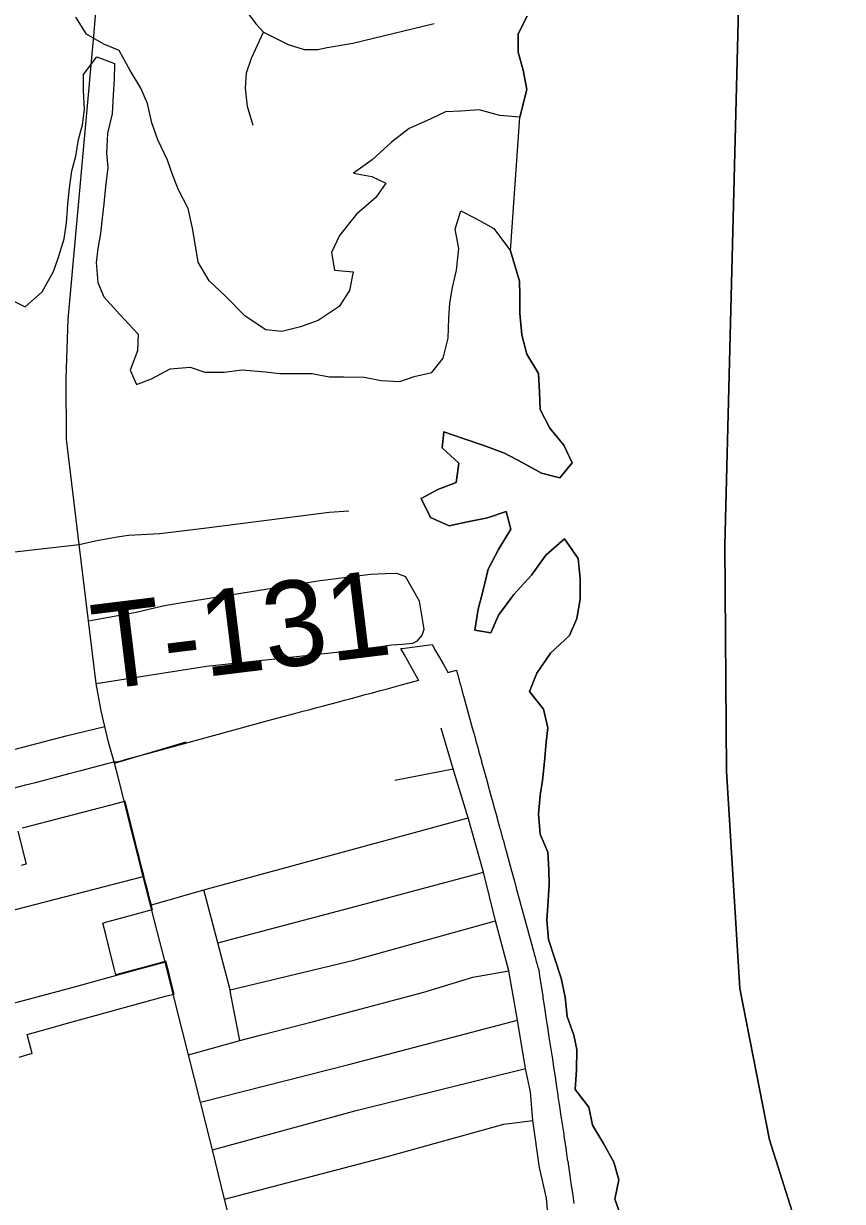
# Model space of a CAD drawing. Extents: x 114843 to 284848, y 317643 to 566895.
# Drawn here: x 167440 to 170319, y 459640 to 463781 of the extents above; entities that cross this region are included whole.
import ezdxf

# ---------------------------------------------------------------- set-up
doc = ezdxf.new("R2010")
doc.units = 0
for name, color, linetype in [('GM_X_City_Street', 7, 'Continuous'), ('GM_X_Corporation', 7, 'Continuous'), ('GM_X_County_Road', 7, 'Continuous'), ('GM_X_Major_Lake', 7, 'Continuous'), ('GM_X_Major_River', 7, 'Continuous'), ('GM_X_State_Route', 7, 'Continuous'), ('GM_X_Township', 7, 'Continuous'), ('GM_X_Township_Road', 7, 'Continuous'), ('GM_X_Township_Road_Text', 7, 'Continuous')]:
    doc.layers.add(name, color=color, linetype=linetype)

msp = doc.modelspace()

# ---------------------------------------------------------------- linework, layer by layer
at = {"layer": 'GM_X_City_Street'}
for p, q in [((168745.7, 461121), (168950.7, 461161.4)), ((168200, 460205.8), (168169.3, 460367.8))]:
    msp.add_line(p, q, dxfattribs=at)
for points in [[(168967.3, 461107.1), (168950.7, 461161.4), (168908.5, 461303.7)], [(169468.8, 458354.7), (169437.7, 458431.6), (169429.4, 458486), (169425.1, 458527.2), (169427.4, 458612.6), (169413.6, 458710.9), (169362.2, 459060.9), (169338.5, 459258.1), (169309.4, 459413), (169285.1, 459584.6), (169278.4, 459651.4), (169254.4, 459760), (169230.9, 459924.5), (169222.5, 460025.5), (169205.1, 460108.1), (169176.3, 460277.9), (169146.9, 460451.4), (169099.9, 460627), (169057.2, 460797.9), (169003.6, 460988.7), (168967.3, 461107.1)], [(167885.9, 460681.7), (168073.6, 460735), (168750, 460920.1), (169003.6, 460988.7)], [(168123.6, 460549.6), (168623.7, 460681.2), (169057.2, 460797.9)], [(168169.3, 460367.8), (168166.2, 460384), (168123.6, 460549.6), (168073.6, 460735)], [(168166.2, 460384), (168601.6, 460488.1), (169099.9, 460627)], [(168989.8, 460418.9), (169020.3, 460428.1), (169146.9, 460451.4)], [(168276.2, 460225.4), (168459, 460272.6), (168847.6, 460376.3), (168989.8, 460418.9)], [(168061.8, 459989.1), (168583.4, 460122), (169176.3, 460277.9)], [(168019.9, 460155.2), (168200, 460205.8), (168276.2, 460225.4)], [(168104.4, 459821.6), (168609.8, 459960.5), (169205.1, 460108.1)], [(168146.6, 459648), (168715.3, 459797), (169128.3, 459911.4), (169230.9, 459924.5)]]:
    msp.add_lwpolyline(points, dxfattribs=at)
at = {"layer": 'GM_X_Corporation'}
for points in [[(167404.1, 461092.8), (167442.9, 461103), (167447.2, 461104.1), (167482.5, 461113.4), (167521.5, 461123.7), (167539.8, 461128.5), (167561.6, 461134.2), (167600.6, 461144.5), (167641.7, 461155.4), (167730, 461178.9), (167732.7, 461179.6), (167739.3, 461181.3), (167761.8, 461187.2), (167762.6, 461183.8), (167791.5, 461191.7), (167797.9, 461193.5), (167902.3, 461222), (168253, 461317.8), (168295.2, 461329.3), (168397.7, 461356.7), (168422.2, 461363.2), (168447.5, 461370), (168471.2, 461376.3), (168494.6, 461382.5), (168543.9, 461395.7), (168568.6, 461402.3), (168592.3, 461408.7), (168618, 461415.5), (168641.3, 461421.7), (168667, 461428.6), (168690.4, 461434.9), (168715.2, 461441.5), (168739.5, 461448), (168763.7, 461454.5), (168829.4, 461472), (168828, 461474.6), (168805.2, 461515.1), (168792.3, 461538.1), (168779.3, 461561.3), (168767, 461583.3), (168771.1, 461583.8), (168877.1, 461597.5), (168889, 461576.2), (168902.2, 461552.7), (168915.2, 461529.6), (168930.4, 461502.6), (168932.1, 461499.4), (168962, 461507.4), (168964.8, 461497.7), (168965.7, 461494.5), (168975.6, 461459), (168976.5, 461455.7), (168986.3, 461420.3), (168987.2, 461417.1), (168996.8, 461382.2), (168997.6, 461379), (169007.4, 461343.6), (169008.3, 461340.4), (169018, 461305), (169018.9, 461301.8), (169028.6, 461266.4), (169029.5, 461263.1), (169039.3, 461227.6), (169040.2, 461224.3), (169049.9, 461189), (169050.8, 461185.8), (169060.9, 461148.8), (169061.8, 461145.6), (169071, 461112.1), (169071.5, 461110.3), (169082.4, 461070.7), (169092.4, 461034.1), (169092.8, 461032.3), (169103.6, 460992.9), (169104.1, 460991.1), (169115.1, 460951), (169115.6, 460949.2), (169125.6, 460912.6), (169126.1, 460910.8), (169136, 460874.7), (169136.5, 460873), (169147.6, 460832.3), (169155.7, 460802.6), (169156.8, 460798.8), (169164.7, 460769.8), (169165.7, 460766), (169173.8, 460736.5), (169174.9, 460732.7), (169183, 460702.8), (169184.1, 460699), (169192.4, 460668.7), (169193.4, 460664.9), (169201.5, 460635.3), (169202.5, 460631.7), (169210.8, 460601.4), (169211.8, 460597.6), (169217.9, 460575.4), (169220.1, 460567.3), (169221.2, 460563.5), (169229.5, 460533.1), (169237.7, 460503), (169238.8, 460499.2), (169242.9, 460484), (169244.6, 460478), (169248.7, 460462.7), (169249.3, 460461), (169251.6, 460453.3), (169255.9, 460425), (169261.1, 460391.2), (169265.5, 460362.4), (169266.4, 460356.3), (169271.6, 460322), (169277, 460287.3), (169281.4, 460258.4), (169282.3, 460252.3), (169287.5, 460217.9), (169292.9, 460183), (169297.3, 460154.2), (169298.2, 460148), (169303.5, 460113.3), (169307.8, 460084.4), (169308.8, 460078.2), (169314, 460043.4), (169318.3, 460014.9), (169319.2, 460008.7), (169324.4, 459974.2), (169329.6, 459939.8), (169333.9, 459911.7), (169334.8, 459905.3), (169339.2, 459876.6), (169340.1, 459870.2), (169345.3, 459835.7), (169350.6, 459799.4), (169352, 459790.1), (169352.9, 459783.7), (169353.3, 459781.4), (169355.8, 459764.1), (169360.5, 459732), (169364.6, 459703.9), (169365.5, 459697.5), (169370.8, 459661.5), (169374.9, 459632.9)], [(167424.2, 460147.9), (167463.3, 460158.8), (167469.9, 460160.6), (167452.9, 460227.4), (167524.7, 460247.2), (167602.3, 460268.7), (167938.9, 460361.7), (167969.9, 460368.7), (167959.1, 460410.4), (167950.3, 460444.5), (167940, 460484.4), (167908.7, 460475.8), (167764.6, 460436.3), (167759.5, 460455.7), (167749.2, 460497.1), (167739.5, 460535.8), (167729, 460578.2), (167718.9, 460618.7), (167733.1, 460622.6), (167767.9, 460632.3), (167862.7, 460658.8), (167892.9, 460666.4), (167888.2, 460685.1), (167884.2, 460701.1), (167875.7, 460735), (167865.6, 460774.7), (167862.9, 460785.5), (167856.4, 460811.2), (167847.7, 460845.8), (167838.8, 460881.2), (167830.1, 460915.7), (167817.3, 460966.6), (167804.2, 461018.8), (167797.7, 461046.8), (167769.6, 461039.6), (167435, 460951.8)], [(167419.5, 460941.6), (167449.4, 460826.1), (167447.6, 460825.6), (167431.7, 460821.3)]]:
    msp.add_lwpolyline(points, dxfattribs=at)
at = {"layer": 'GM_X_County_Road'}
msp.add_lwpolyline([(166273, 461789.7), (166413.7, 461807.2), (166482.1, 461815), (166760.2, 461849.3), (166977.2, 461874.1), (167064.3, 461883.6), (167229, 461903.7), (167325.4, 461914.8), (167635.9, 461949.3)], dxfattribs=at)
at = {"layer": 'GM_X_Major_Lake'}
msp.add_line((169152.1, 462982.1), (169185.5, 463451), dxfattribs=at)
for points in [[(169185.5, 463451), (169209.4, 463548.3), (169197.2, 463616.4), (169179, 463680.5), (169178.8, 463744.5), (169210.7, 463806.7)], [(169541.6, 459585.7), (169519.4, 459647.8), (169533.2, 459716), (169515, 459778), (169478.7, 459844.1), (169440.4, 459908.1), (169428.2, 459972.2), (169379.9, 460034.2), (169383.7, 460102.4), (169385.5, 460174.5), (169375.3, 460224.6), (169351.1, 460290.7), (169344.9, 460358.8), (169330.6, 460424.9), (169306.4, 460497), (169286.1, 460561.1), (169279.9, 460629.2), (169283.8, 460679.3), (169287.6, 460753.5), (169287.4, 460805.5), (169283.3, 460867.7), (169257, 460931.7), (169250.8, 461001.9), (169256.6, 461068), (169264.5, 461120.1), (169272.3, 461186.3), (169278.1, 461254.4), (169284, 461304.5), (169267.8, 461370.6), (169219.5, 461432.6), (169245.3, 461496.8), (169293.3, 461567.1), (169359.3, 461629.3), (169385.2, 461689.5), (169397, 461757.7), (169396.8, 461829.8), (169390.6, 461899.9), (169342.3, 461969.9), (169276.2, 461911.7), (169226.3, 461841.4), (169164.3, 461773.1), (169110.4, 461700.8), (169082.5, 461638.7), (169026.3, 461648.5), (169038.2, 461722.7), (169056, 461788.9), (169073.8, 461863.1), (169109.8, 461931.3), (169153.7, 462003.5), (169137.4, 462065.6), (169071.3, 462043.4), (169001.2, 462029.2), (168937, 462015), (168870.8, 462044.9), (168838.5, 462110.9), (168896.6, 462143.1), (168960.7, 462167.3), (168970.5, 462235.5), (168912.2, 462289.4), (168918.1, 462345.5), (168986.3, 462321.7), (169058.6, 462297.8), (169130.8, 462269.9), (169195.1, 462236.1), (169261.4, 462200.2), (169325.6, 462184.3), (169369.6, 462236.5), (169339.3, 462298.5), (169291, 462358.5), (169256.7, 462424.5), (169254.6, 462484.7), (169250.4, 462550.8), (169210.1, 462618.8), (169191.8, 462686.8), (169185.6, 462761), (169185.4, 462825.1), (169183.3, 462875.1), (169152.1, 462982.1)]]:
    msp.add_lwpolyline(points, dxfattribs=at)
at = {"layer": 'GM_X_Major_River'}
msp.add_line((169152.1, 462982.1), (169185.5, 463451), dxfattribs=at)
for points in [[(168523, 462975.7), (168533.4, 462913.7), (168599.5, 462907.9), (168585.8, 462841.8), (168550, 462785.5), (168476, 462737.1), (168414, 462714.8), (168347.9, 462698.4), (168291.7, 462704.2), (168219.3, 462752), (168148.9, 462823.8), (168092.5, 462875.7), (168054.1, 462941.7), (168045.9, 462991.7), (168033.6, 463061.8), (168019.2, 463129.9), (167984.9, 463195.8), (167964.6, 463245.9), (167946.3, 463299.9), (167911.9, 463371.9), (167891.6, 463431.9), (167875.3, 463500), (167853, 463554), (167814.6, 463615.9), (167776.3, 463685.9), (167722, 463707.7), (167661.7, 463743.5), (167623.4, 463803.4)], [(169210.7, 463806.7), (169178.8, 463744.5), (169179, 463680.5), (169197.2, 463616.4), (169209.4, 463548.3), (169185.5, 463451)], [(167377.1, 462820.5), (167445.4, 462784.7), (167505.4, 462837.1), (167545.1, 462909.4), (167562.9, 462959.6), (167582.7, 463023.8), (167590.5, 463079.9), (167596.2, 463146.1), (167602, 463202.2), (167609.7, 463262.4), (167623.5, 463314.5), (167633.3, 463372.7), (167647.1, 463424.8), (167654.9, 463479), (167650.6, 463545.1), (167650.3, 463601.2), (167698.2, 463663.5), (167760.4, 463639.7), (167758.7, 463583.6), (167754.9, 463529.5), (167751.2, 463463.3), (167735.4, 463395.2), (167731.7, 463325), (167736, 463274.9), (167728.2, 463206.8), (167722.5, 463146.6), (167716.7, 463096.5), (167710.9, 463042.4), (167701.1, 462990.2), (167695.3, 462940.1), (167701.7, 462870), (167721.9, 462820), (167778.3, 462758.1), (167842.8, 462688.2), (167841, 462630.1), (167815.3, 462561.9), (167837.5, 462511.9), (167889.6, 462532.1), (167955.6, 462566.5), (168025.7, 462572.8), (168077.9, 462555), (168146, 462555.3), (168208.1, 462563.6), (168290.4, 462555.9), (168340.5, 462550.1), (168454.8, 462550.6), (168515, 462538.8), (168565.1, 462539.1), (168637.2, 462537.4), (168697.4, 462525.6), (168763.6, 462521.9), (168813.6, 462540.1), (168875.7, 462554.4), (168915.6, 462604.7), (168933.3, 462674.9), (168935, 462745), (168938.8, 462797.2), (168948.6, 462853.3), (168962.3, 462913.5), (168970, 462989.7), (168957.7, 463057.8), (168977.4, 463122), (169027.7, 463096.1), (169094, 463060.4), (169152.1, 462982.1)], [(169185.5, 463451), (169114.3, 463457.2), (169042, 463476.9), (168975.9, 463472.6), (168923.8, 463470.4), (168871.8, 463446.1), (168795.8, 463411.7), (168733.8, 463363.4), (168666, 463301), (168600, 463254.6), (168664.2, 463242.9), (168714.4, 463219), (168678.6, 463168.8), (168610.7, 463110.4), (168550.9, 463036), (168523, 462975.7)], [(169152.1, 462982.1), (169183.3, 462875.1), (169185.4, 462825.1), (169185.6, 462761), (169191.8, 462686.8), (169210.1, 462618.8), (169250.4, 462550.8), (169254.6, 462484.7), (169256.7, 462424.5), (169291, 462358.5), (169339.3, 462298.5), (169369.6, 462236.5), (169325.6, 462184.3), (169261.4, 462200.2), (169195.1, 462236.1), (169130.8, 462269.9), (169058.6, 462297.8), (168986.3, 462321.7), (168918.1, 462345.5), (168912.2, 462289.4), (168970.5, 462235.5), (168960.7, 462167.3), (168896.6, 462143.1), (168838.5, 462110.9), (168870.8, 462044.9), (168937, 462015), (169001.2, 462029.2), (169071.3, 462043.4), (169137.4, 462065.6), (169153.7, 462003.5), (169109.8, 461931.3), (169073.8, 461863.1), (169056, 461788.9), (169038.2, 461722.7), (169026.3, 461648.5), (169082.5, 461638.7), (169110.4, 461700.8), (169164.3, 461773.1), (169226.3, 461841.4), (169276.2, 461911.7), (169342.3, 461969.9), (169390.6, 461899.9), (169396.8, 461829.8), (169397, 461757.7), (169385.2, 461689.5), (169359.3, 461629.3), (169293.3, 461567.1), (169245.3, 461496.8), (169219.5, 461432.6), (169267.8, 461370.6), (169284, 461304.5), (169278.1, 461254.4), (169272.3, 461186.3), (169264.5, 461120.1), (169256.6, 461068), (169250.8, 461001.9), (169257, 460931.7), (169283.3, 460867.7), (169287.4, 460805.5), (169287.6, 460753.5), (169283.8, 460679.3), (169279.9, 460629.2), (169286.1, 460561.1), (169306.4, 460497), (169330.6, 460424.9), (169344.9, 460358.8), (169351.1, 460290.7), (169375.3, 460224.6), (169385.5, 460174.5), (169383.7, 460102.4), (169379.9, 460034.2), (169428.2, 459972.2), (169440.4, 459908.1), (169478.7, 459844.1), (169515, 459778), (169533.2, 459716), (169519.4, 459647.8), (169541.6, 459585.7)]]:
    msp.add_lwpolyline(points, dxfattribs=at)
at = {"layer": 'GM_X_State_Route'}
for p, q in [((167772.5, 461131.6), (167760.2, 461180.6)), ((167937.6, 460481.2), (167890.6, 460663.2))]:
    msp.add_line(p, q, dxfattribs=at)
for points in [[(167635.9, 461949.3), (167591.6, 462319.5), (167590, 462533.3), (167597.3, 462741.3), (167686.7, 463737.7), (167703.4, 463934.8), (167709, 464038.6), (167709.4, 464115.9), (167703.7, 464198.9), (167694, 464266.3), (167673.3, 464361.9), (167647.6, 464451.9), (167583.1, 464670), (167517, 464881.3), (167489.3, 464979.8)], [(167760.2, 461180.6), (167739.3, 461254.6), (167725.9, 461310.2), (167712.4, 461364.5), (167694.8, 461461.1), (167668.5, 461680.8), (167635.9, 461949.3)], [(167797.3, 461033.4), (167794.8, 461043.4), (167772.5, 461131.6)], [(167890.6, 460663.2), (167885.9, 460681.7), (167860.6, 460782.1), (167797.3, 461033.4)], [(167976, 460331.2), (167967.5, 460365.4), (167937.6, 460481.2)], [(168657.6, 457655.7), (168627.7, 457758.9), (168586.4, 457940.7), (168545.7, 458118.1), (168494, 458294.5), (168448.5, 458464.7), (168404.3, 458632.6), (168361.5, 458806.3), (168322.4, 458954.2), (168320.9, 458959.6), (168275.3, 459138.1), (168234.7, 459303), (168233.1, 459309.3), (168187.6, 459488.1), (168146.6, 459648), (168104.4, 459821.6), (168061.8, 459989.1), (168019.9, 460155.2), (167976, 460331.2)]]:
    msp.add_lwpolyline(points, dxfattribs=at)
at = {"layer": 'GM_X_Township'}
for points in [[(170803.8, 457703.8), (170250.2, 459264.1), (170063.2, 459856.3), (169958.9, 460388.9), (169911.1, 461152.6), (169905.4, 461946.5), (169968.1, 464386.5)], [(169968.1, 464386.5), (169905.4, 461946.5), (169911.1, 461152.6), (169958.9, 460388.9), (170063.2, 459856.3), (170250.2, 459264.1), (170803.8, 457703.8)]]:
    msp.add_lwpolyline(points, dxfattribs=at)
at = {"layer": 'GM_X_Township_Road'}
for p, q in [((167760.2, 461180.6), (168011.8, 461255.9)), ((166970, 460553.4), (167860.6, 460782.1)), ((167937.6, 460481.2), (167791.4, 460441.1))]:
    msp.add_line(p, q, dxfattribs=at)
for points in [[(167673.3, 464361.9), (167753.4, 464393.8), (167822.3, 464400), (167899.6, 464389.5), (167937.8, 464376.4), (167990.6, 464347.9), (168021.6, 464319.3), (168051.8, 464284.5), (168084.1, 464231.2), (168139, 464077.5), (168183.1, 463915.6), (168219.1, 463830.1), (168256.6, 463780.1), (168284, 463750), (168370.3, 463707.1), (168426.3, 463689.8), (168474.8, 463689.2), (168507.3, 463695.9), (168597.7, 463712), (168883.3, 463780.5)], [(168247.6, 463421.8), (168227.5, 463489), (168220.5, 463553.2), (168223.6, 463606.8), (168241.9, 463658.8), (168284, 463750)], [(167635.9, 461949.3), (167691.9, 461962.1), (167769.4, 461975.9), (167808.5, 461982.2), (167919.2, 461988.4), (168092.9, 462009.5), (168515, 462062.5), (168583.2, 462068)], [(167668.5, 461680.8), (167836.3, 461712.1), (167929.9, 461734.1), (167991.3, 461744.3), (168482.6, 461822.6), (168660.2, 461845.2), (168711.7, 461848), (168751, 461848.3), (168783.4, 461837.3)], [(168809.2, 461602.7), (168825, 461611.3), (168841.8, 461630.9), (168849, 461651.6), (168832.8, 461750.6), (168783.4, 461837.3)], [(167694.8, 461461.1), (168083.2, 461521.5), (168627.8, 461579.8), (168733.3, 461596.9), (168771.8, 461598.8), (168809.2, 461602.7)], [(165587.3, 460763.7), (165651.6, 460768.2), (165729.6, 460783.4), (165885.5, 460832.6), (166342.3, 460956.6), (166974.5, 461116.1), (167589.5, 461276.9), (167725.9, 461310.2)], [(167791.4, 460441.1), (167762.2, 460433.1), (167597, 460387.5), (166421.9, 460074.7)]]:
    msp.add_lwpolyline(points, dxfattribs=at)

# ---------------------------------------------------------------- texts
at = {"layer": 'GM_X_Township_Road_Text'}
msp.add_text('T-131', height=300, rotation=6.9944, dxfattribs=at).set_placement((167701.9, 461437.4))

doc.saveas('drawing.dxf')
